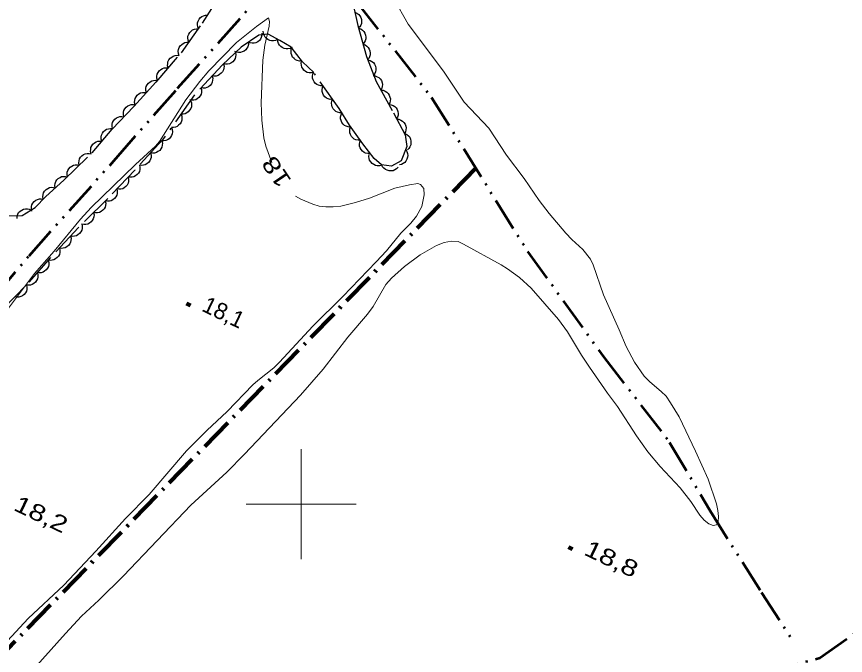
# Model space of a CAD drawing. Extents: x 355726 to 357533, y 5103782 to 5105258.
# Drawn here: x 356374.1 to 356449.5, y 5104986.2 to 5105044.4 of the extents above; entities that cross this region are included whole.
import ezdxf
from ezdxf.enums import TextEntityAlignment as Align

# ---------------------------------------------------------------- set-up
doc = ezdxf.new("R2010")
doc.units = 0
doc.header["$LTSCALE"] = 0.6
for name, pattern in [('DASH_DOUBLE_DOT', [9.2, 5, -1.2, 0.3, -1.2, 0.3, -1.2]), ('DOT_DASHED', [7.7, 5, -1.2, 0.3, -1.2]), ('LONG_DASHED', [7.5, 6, -1.5])]:
    doc.linetypes.add(name, pattern=pattern)
for name, color, linetype, lineweight in [('2', 7, 'LONG_DASHED', 13), ('3', 7, 'Continuous', 140), ('4', 7, 'DASH_DOUBLE_DOT', 53), ('41', 7, 'DOT_DASHED', 90), ('44', 7, 'Continuous', 25), ('61', 7, 'Continuous', 13)]:
    doc.layers.add(name, color=color, linetype=linetype, lineweight=lineweight)

msp = doc.modelspace()

# ---------------------------------------------------------------- linework, layer by layer
at = {"layer": '2', "linetype": 'Continuous'}
for points in [[(356437.94, 5104998.86), (356437.9, 5104999.41), (356437.77, 5105000.04), (356437.01, 5105002.26), (356435.85, 5105004.82), (356434.36, 5105007.93), (356433.6, 5105009.23), (356433.2, 5105009.82), (356432.74, 5105010.26), (356431.7, 5105011.12), (356431.18, 5105011.65), (356430.3, 5105012.92), (356429.56, 5105014.33), (356428.93, 5105015.87), (356427.5, 5105019.05), (356426.55, 5105021.78), (356426.3, 5105022.29), (356425.6, 5105023.16), (356424.6, 5105024.09), (356424.07, 5105024.65), (356422.55, 5105026.46), (356421.65, 5105027.63), (356420.28, 5105029.62), (356418.66, 5105031.76), (356417.05, 5105034.22), (356414.81, 5105036.58), (356412.94, 5105039.41), (356409.72, 5105043.69), (356405.81, 5105050.63)], [(356372.83, 5105017.09), (356375.75, 5105020.98), (356377.54, 5105023.01), (356379.92, 5105025.92), (356380.9, 5105026.98), (356384.92, 5105030.9), (356386.75, 5105032.59), (356387.11, 5105032.99), (356389.51, 5105036.8), (356390.77, 5105038.46), (356391.61, 5105039.43), (356394.12, 5105042), (356395.92, 5105043.46), (356397.03, 5105044.24), (356397.12, 5105043.92), (356397.07, 5105043.51), (356396.7, 5105041.76), (356396.52, 5105040.41), (356396.35, 5105036.51), (356396.41, 5105034.93), (356396.6, 5105033.34), (356396.79, 5105032.59), (356397.34, 5105031.09)], [(356399.48, 5105028.03), (356399.96, 5105027.76), (356401.05, 5105027.29), (356401.62, 5105027.13), (356402.24, 5105027.05), (356402.92, 5105027.04), (356403.59, 5105027.13), (356404.94, 5105027.45), (356406.21, 5105027.84), (356408.52, 5105028.74), (356409.85, 5105029.07), (356410.6, 5105029.17), (356410.86, 5105029.08), (356411.15, 5105028.73), (356411.19, 5105028.16), (356410.96, 5105027.09), (356410.47, 5105026.2), (356409.96, 5105025.58), (356409.07, 5105024.67), (356407.75, 5105023.05), (356406.83, 5105022.05), (356403.79, 5105018.88), (356401.06, 5105016.19), (356398.02, 5105012.92), (356397.5, 5105012.41), (356396.05, 5105011.26), (356395.61, 5105010.86), (356393.25, 5105008.43), (356391.41, 5105006.7), (356389.56, 5105004.84), (356386.18, 5105000.88), (356384.02, 5104998.69), (356381.33, 5104995.71), (356378.42, 5104992.63), (356375.16, 5104989.59), (356369.89, 5104983.93)], [(356375.16, 5104984.42), (356378.55, 5104988.22), (356380.03, 5104989.79), (356381.6, 5104991.26), (356383.84, 5104993.47), (356389.97, 5104999.91), (356393.22, 5105002.9), (356394.84, 5105004.55), (356399.94, 5105009.93), (356402, 5105012.29), (356404.24, 5105015.18), (356406.04, 5105017.3), (356406.53, 5105017.98), (356407.71, 5105019.98), (356408.2, 5105020.55), (356409.4, 5105021.63), (356410.81, 5105022.68), (356412.29, 5105023.54), (356413, 5105023.8), (356413.66, 5105023.94), (356414.27, 5105023.9), (356414.76, 5105023.67), (356418.2, 5105021.78), (356418.77, 5105021.42), (356419.85, 5105020.63), (356420.91, 5105019.65), (356423.39, 5105016.79), (356424.21, 5105015.67), (356425.49, 5105013.55), (356426.21, 5105012.47), (356427.87, 5105010.09), (356428.77, 5105008.88), (356430.5, 5105006.2), (356431.52, 5105004.76), (356432.65, 5105003.42), (356434.48, 5105001.49), (356435.45, 5105000.23), (356436.26, 5104999.01), (356436.65, 5104998.53), (356437.07, 5104998.21), (356437.46, 5104998.05), (356437.78, 5104998.12), (356437.93, 5104998.4), (356437.94, 5104998.86)]]:
    msp.add_lwpolyline(points, dxfattribs=at)
at = {"layer": '3'}
for p, q in [((356389.57, 5105018.25), (356389.93, 5105018.08)), ((356424.32, 5104996.07), (356424.68, 5104995.9))]:
    msp.add_line(p, q, dxfattribs=at)
at = {"layer": '4'}
for points in [[(356339.44, 5104984.41), (356342.57, 5104987.3), (356345.43, 5104989.4), (356348.27, 5104992.55), (356353.06, 5104997.45), (356357.34, 5105001.22), (356361.27, 5105005.44), (356363.86, 5105008.47), (356365.91, 5105011.22), (356369.21, 5105015.05), (356372.09, 5105018.86), (356375.24, 5105022.59), (356382.96, 5105031.25), (356388.75, 5105037.84), (356397.2, 5105047.28), (356402.63, 5105053.37), (356407.19, 5105058.61), (356412.14, 5105064.26), (356419.11, 5105072.16), (356427.79, 5105081.09)], [(356401.2, 5105051.76), (356405.12, 5105045.59), (356411.86, 5105037.01), (356420.59, 5105022.99), (356427.52, 5105013.38), (356433.51, 5105005.62), (356437.18, 5104999.38), (356441.87, 5104991.96), (356444.63, 5104987.67)], [(356336.18, 5104942.45), (356341.96, 5104947.67), (356347.36, 5104952.78), (356353.47, 5104957.09), (356358.77, 5104960.07), (356366.13, 5104963.5), (356374.65, 5104966.38), (356388.16, 5104970.04), (356447.17, 5104986.01), (356457.01, 5104992.96), (356506.13, 5105036.55), (356518.85, 5105048.42), (356518.86, 5105048.43)]]:
    msp.add_lwpolyline(points, dxfattribs=at)
at = {"layer": '41'}
msp.add_line((356415.87, 5105030.57), (356369.66, 5104983.09), dxfattribs=at)
at = {"layer": '44', "linetype": 'DOT_DASHED'}
for points in [[(356372.21, 5105026.22), (356374.61, 5105026.26), (356375.8, 5105026.98), (356376.78, 5105028.01), (356378.4, 5105029.48), (356380.99, 5105031.98), (356382.8, 5105034.13), (356384.76, 5105036.19), (356386.8, 5105038.41), (356389.1, 5105041.08), (356391.01, 5105043.76), (356392.86, 5105046.68)], [(356404.7, 5105045.58), (356405.14, 5105043.55), (356405.93, 5105040.74), (356406.82, 5105038.46), (356408.38, 5105035.6), (356409.44, 5105033.62), (356409.61, 5105032.54), (356409.08, 5105031.25), (356408.21, 5105030.75), (356407.29, 5105030.87), (356406.62, 5105031.44), (356405.61, 5105032.8), (356404.38, 5105034.48), (356403.45, 5105035.99), (356401.14, 5105039.27), (356400.11, 5105040.24), (356399.09, 5105041.6), (356398.04, 5105042.19), (356396.99, 5105042.78), (356396.13, 5105042.67), (356394.53, 5105041.59), (356392.83, 5105039.97), (356390.3, 5105037.24)], [(356390.3, 5105037.24), (356387.39, 5105033.14), (356384.86, 5105030.4), (356382.41, 5105027.82), (356379.73, 5105025.17), (356377.2, 5105022.44), (356374.99, 5105019.92), (356372.13, 5105016.97), (356369.52, 5105014.09), (356366.65, 5105010.76), (356364.1, 5105007.64), (356353.71, 5104995.88), (356350.22, 5104992.5), (356348.03, 5104990.37), (356346, 5104988.54), (356344.73, 5104987.67), (356343.7, 5104987.26), (356342.4, 5104987.4), (356341.65, 5104987.82), (356341.06, 5104988.54), (356341, 5104988.78), (356340.94, 5104990.79)]]:
    msp.add_lwpolyline(points, dxfattribs=at)
at = {"layer": '44'}
for points in [[(356404.88, 5105044.77), (356405.07, 5105044.69), (356405.23, 5105044.56), (356405.34, 5105044.44), (356405.42, 5105044.29), (356405.48, 5105044.11), (356405.49, 5105043.92), (356405.48, 5105043.75), (356405.41, 5105043.59), (356405.32, 5105043.43), (356405.19, 5105043.3)], [(356390.68, 5105043.23), (356390.59, 5105043.43), (356390.57, 5105043.63), (356390.57, 5105043.79), (356390.63, 5105043.96), (356390.71, 5105044.12), (356390.84, 5105044.27), (356390.96, 5105044.38), (356391.12, 5105044.45), (356391.3, 5105044.5), (356391.48, 5105044.5)], [(356389.78, 5105042.03), (356389.71, 5105042.23), (356389.69, 5105042.43), (356389.7, 5105042.6), (356389.77, 5105042.76), (356389.86, 5105042.92), (356390, 5105043.05), (356390.12, 5105043.16), (356390.29, 5105043.22), (356390.47, 5105043.26), (356390.65, 5105043.25)], [(356405.21, 5105043.3), (356405.41, 5105043.24), (356405.57, 5105043.12), (356405.69, 5105043.01), (356405.78, 5105042.86), (356405.85, 5105042.68), (356405.87, 5105042.49), (356405.87, 5105042.33), (356405.82, 5105042.16), (356405.73, 5105042), (356405.62, 5105041.86)], [(356396.43, 5105042.87), (356396.43, 5105042.67), (356396.37, 5105042.47), (356396.3, 5105042.32), (356396.19, 5105042.19), (356396.05, 5105042.07), (356395.87, 5105041.99), (356395.72, 5105041.94), (356395.54, 5105041.94), (356395.36, 5105041.97), (356395.19, 5105042.04)], [(356397.86, 5105042.29), (356397.67, 5105042.2), (356397.47, 5105042.16), (356397.31, 5105042.16), (356397.14, 5105042.2), (356396.97, 5105042.28), (356396.82, 5105042.4), (356396.71, 5105042.51), (356396.62, 5105042.67), (356396.57, 5105042.85), (356396.55, 5105043.03)], [(356388.91, 5105040.81), (356388.83, 5105041.01), (356388.82, 5105041.21), (356388.83, 5105041.37), (356388.9, 5105041.54), (356388.99, 5105041.7), (356389.13, 5105041.83), (356389.25, 5105041.93), (356389.42, 5105042), (356389.6, 5105042.04), (356389.78, 5105042.03)], [(356395.19, 5105042.04), (356395.19, 5105041.83), (356395.13, 5105041.63), (356395.06, 5105041.48), (356394.95, 5105041.35), (356394.8, 5105041.23), (356394.63, 5105041.15), (356394.47, 5105041.1), (356394.3, 5105041.1), (356394.11, 5105041.13), (356393.95, 5105041.2)], [(356399.17, 5105041.56), (356398.98, 5105041.46), (356398.78, 5105041.43), (356398.62, 5105041.42), (356398.45, 5105041.47), (356398.28, 5105041.54), (356398.13, 5105041.66), (356398.01, 5105041.78), (356397.93, 5105041.93), (356397.88, 5105042.11), (356397.86, 5105042.29)], [(356405.62, 5105041.86), (356405.81, 5105041.79), (356405.98, 5105041.68), (356406.1, 5105041.56), (356406.19, 5105041.41), (356406.25, 5105041.24), (356406.28, 5105041.05), (356406.28, 5105040.89), (356406.22, 5105040.72), (356406.14, 5105040.55), (356406.02, 5105040.42)], [(356387.9, 5105039.69), (356387.85, 5105039.89), (356387.86, 5105040.1), (356387.88, 5105040.26), (356387.96, 5105040.42), (356388.07, 5105040.57), (356388.22, 5105040.69), (356388.35, 5105040.78), (356388.52, 5105040.83), (356388.71, 5105040.85), (356388.88, 5105040.83)], [(356394.02, 5105041.1), (356394.06, 5105040.9), (356394.03, 5105040.7), (356393.99, 5105040.54), (356393.89, 5105040.39), (356393.77, 5105040.25), (356393.61, 5105040.14), (356393.47, 5105040.07), (356393.3, 5105040.03), (356393.11, 5105040.03), (356392.93, 5105040.07)], [(356400.04, 5105040.33), (356399.84, 5105040.32), (356399.64, 5105040.37), (356399.48, 5105040.43), (356399.35, 5105040.54), (356399.22, 5105040.68), (356399.14, 5105040.85), (356399.08, 5105041), (356399.07, 5105041.17), (356399.09, 5105041.36), (356399.14, 5105041.53)], [(356401.12, 5105039.29), (356400.92, 5105039.24), (356400.72, 5105039.26), (356400.55, 5105039.29), (356400.4, 5105039.37), (356400.25, 5105039.49), (356400.14, 5105039.64), (356400.05, 5105039.78), (356400.01, 5105039.95), (356400, 5105040.14), (356400.03, 5105040.32)], [(356406.05, 5105040.43), (356406.26, 5105040.38), (356406.43, 5105040.28), (356406.56, 5105040.18), (356406.67, 5105040.04), (356406.75, 5105039.87), (356406.79, 5105039.68), (356406.8, 5105039.52), (356406.77, 5105039.35), (356406.7, 5105039.18), (356406.6, 5105039.03)], [(356386.93, 5105038.56), (356386.87, 5105038.76), (356386.88, 5105038.96), (356386.9, 5105039.12), (356386.98, 5105039.28), (356387.09, 5105039.43), (356387.24, 5105039.55), (356387.37, 5105039.64), (356387.54, 5105039.69), (356387.73, 5105039.71), (356387.9, 5105039.69)], [(356392.93, 5105040.08), (356392.98, 5105039.87), (356392.96, 5105039.67), (356392.93, 5105039.51), (356392.85, 5105039.35), (356392.73, 5105039.21), (356392.58, 5105039.09), (356392.44, 5105039), (356392.27, 5105038.96), (356392.09, 5105038.95), (356391.91, 5105038.98)], [(356385.92, 5105037.45), (356385.87, 5105037.65), (356385.88, 5105037.85), (356385.91, 5105038.02), (356385.99, 5105038.17), (356386.11, 5105038.32), (356386.26, 5105038.44), (356386.4, 5105038.52), (356386.57, 5105038.56), (356386.75, 5105038.58), (356386.93, 5105038.55)], [(356391.91, 5105038.98), (356391.96, 5105038.77), (356391.94, 5105038.57), (356391.91, 5105038.41), (356391.83, 5105038.25), (356391.71, 5105038.11), (356391.56, 5105037.99), (356391.42, 5105037.9), (356391.25, 5105037.86), (356391.07, 5105037.85), (356390.89, 5105037.88)], [(356401.99, 5105038.06), (356401.78, 5105038.06), (356401.58, 5105038.12), (356401.43, 5105038.18), (356401.3, 5105038.29), (356401.18, 5105038.44), (356401.1, 5105038.61), (356401.04, 5105038.76), (356401.04, 5105038.94), (356401.06, 5105039.12), (356401.13, 5105039.29)], [(356406.53, 5105039), (356406.74, 5105038.98), (356406.92, 5105038.9), (356407.07, 5105038.82), (356407.19, 5105038.69), (356407.29, 5105038.54), (356407.35, 5105038.35), (356407.39, 5105038.19), (356407.37, 5105038.02), (356407.33, 5105037.84), (356407.25, 5105037.68)], [(356390.89, 5105037.88), (356390.94, 5105037.67), (356390.92, 5105037.47), (356390.89, 5105037.31), (356390.81, 5105037.15), (356390.69, 5105037.01), (356390.54, 5105036.89), (356390.4, 5105036.8), (356390.23, 5105036.76), (356390.05, 5105036.75), (356389.87, 5105036.78)], [(356402.85, 5105036.84), (356402.64, 5105036.83), (356402.45, 5105036.89), (356402.3, 5105036.95), (356402.16, 5105037.07), (356402.04, 5105037.21), (356401.96, 5105037.38), (356401.91, 5105037.54), (356401.9, 5105037.71), (356401.93, 5105037.9), (356401.99, 5105038.06)], [(356384.9, 5105036.34), (356384.85, 5105036.55), (356384.87, 5105036.75), (356384.9, 5105036.91), (356384.98, 5105037.07), (356385.09, 5105037.21), (356385.24, 5105037.33), (356385.38, 5105037.42), (356385.55, 5105037.46), (356385.74, 5105037.47), (356385.92, 5105037.45)], [(356407.25, 5105037.68), (356407.45, 5105037.66), (356407.64, 5105037.58), (356407.78, 5105037.5), (356407.91, 5105037.37), (356408.01, 5105037.22), (356408.07, 5105037.04), (356408.11, 5105036.88), (356408.09, 5105036.7), (356408.05, 5105036.52), (356407.96, 5105036.36)], [(356383.87, 5105035.25), (356383.82, 5105035.46), (356383.84, 5105035.66), (356383.88, 5105035.82), (356383.96, 5105035.98), (356384.08, 5105036.12), (356384.23, 5105036.24), (356384.37, 5105036.32), (356384.54, 5105036.36), (356384.73, 5105036.37), (356384.9, 5105036.34)], [(356389.93, 5105036.72), (356390.01, 5105036.53), (356390.02, 5105036.32), (356390.01, 5105036.16), (356389.95, 5105036), (356389.85, 5105035.84), (356389.72, 5105035.7), (356389.59, 5105035.6), (356389.43, 5105035.53), (356389.25, 5105035.5), (356389.07, 5105035.5)], [(356403.72, 5105035.61), (356403.51, 5105035.61), (356403.31, 5105035.66), (356403.16, 5105035.73), (356403.03, 5105035.84), (356402.91, 5105035.98), (356402.82, 5105036.16), (356402.77, 5105036.31), (356402.76, 5105036.49), (356402.79, 5105036.67), (356402.85, 5105036.84)], [(356407.96, 5105036.36), (356408.17, 5105036.34), (356408.36, 5105036.27), (356408.5, 5105036.18), (356408.62, 5105036.06), (356408.73, 5105035.9), (356408.79, 5105035.72), (356408.82, 5105035.56), (356408.81, 5105035.39), (356408.76, 5105035.21), (356408.68, 5105035.05)], [(356404.48, 5105034.32), (356404.27, 5105034.33), (356404.08, 5105034.39), (356403.93, 5105034.47), (356403.8, 5105034.59), (356403.69, 5105034.74), (356403.62, 5105034.92), (356403.58, 5105035.07), (356403.58, 5105035.25), (356403.62, 5105035.43), (356403.69, 5105035.6)], [(356382.84, 5105034.17), (356382.79, 5105034.37), (356382.81, 5105034.57), (356382.84, 5105034.74), (356382.93, 5105034.89), (356383.04, 5105035.03), (356383.19, 5105035.15), (356383.34, 5105035.23), (356383.51, 5105035.27), (356383.69, 5105035.28), (356383.87, 5105035.25)], [(356389.07, 5105035.5), (356389.14, 5105035.3), (356389.15, 5105035.1), (356389.14, 5105034.94), (356389.08, 5105034.77), (356388.98, 5105034.61), (356388.85, 5105034.48), (356388.72, 5105034.37), (356388.56, 5105034.31), (356388.38, 5105034.27), (356388.2, 5105034.28)], [(356408.68, 5105035.04), (356408.89, 5105035.02), (356409.07, 5105034.94), (356409.22, 5105034.86), (356409.34, 5105034.73), (356409.44, 5105034.58), (356409.5, 5105034.39), (356409.53, 5105034.24), (356409.52, 5105034.06), (356409.47, 5105033.88), (356409.39, 5105033.72)], [(356381.87, 5105033.02), (356381.81, 5105033.22), (356381.81, 5105033.43), (356381.84, 5105033.59), (356381.91, 5105033.75), (356382.02, 5105033.9), (356382.17, 5105034.02), (356382.3, 5105034.12), (356382.47, 5105034.16), (356382.65, 5105034.19), (356382.83, 5105034.17)], [(356388.2, 5105034.28), (356388.27, 5105034.08), (356388.28, 5105033.88), (356388.27, 5105033.71), (356388.21, 5105033.55), (356388.12, 5105033.39), (356387.98, 5105033.25), (356387.85, 5105033.15), (356387.69, 5105033.09), (356387.51, 5105033.05), (356387.33, 5105033.05)], [(356405.38, 5105033.12), (356405.17, 5105033.11), (356404.97, 5105033.16), (356404.82, 5105033.22), (356404.68, 5105033.33), (356404.56, 5105033.47), (356404.48, 5105033.64), (356404.42, 5105033.8), (356404.41, 5105033.97), (356404.43, 5105034.16), (356404.49, 5105034.33)], [(356409.42, 5105033.73), (356409.61, 5105033.64), (356409.76, 5105033.51), (356409.87, 5105033.38), (356409.94, 5105033.22), (356409.98, 5105033.04), (356409.98, 5105032.85), (356409.96, 5105032.69), (356409.89, 5105032.53), (356409.79, 5105032.37), (356409.66, 5105032.25)], [(356380.9, 5105031.87), (356380.84, 5105032.08), (356380.85, 5105032.28), (356380.87, 5105032.44), (356380.95, 5105032.6), (356381.05, 5105032.75), (356381.2, 5105032.88), (356381.34, 5105032.97), (356381.5, 5105033.02), (356381.69, 5105033.04), (356381.87, 5105033.02)], [(356387.32, 5105033.06), (356387.37, 5105032.86), (356387.35, 5105032.66), (356387.32, 5105032.49), (356387.24, 5105032.34), (356387.13, 5105032.19), (356386.97, 5105032.08), (356386.83, 5105031.99), (356386.66, 5105031.95), (356386.48, 5105031.93), (356386.3, 5105031.96)], [(356406.27, 5105031.91), (356406.06, 5105031.9), (356405.86, 5105031.95), (356405.71, 5105032.01), (356405.57, 5105032.12), (356405.45, 5105032.26), (356405.36, 5105032.43), (356405.31, 5105032.58), (356405.3, 5105032.76), (356405.32, 5105032.95), (356405.38, 5105033.11)], [(356379.81, 5105030.84), (356379.78, 5105031.05), (356379.8, 5105031.25), (356379.84, 5105031.41), (356379.93, 5105031.56), (356380.05, 5105031.7), (356380.21, 5105031.81), (356380.36, 5105031.88), (356380.53, 5105031.92), (356380.71, 5105031.92), (356380.89, 5105031.88)], [(356386.3, 5105031.96), (356386.35, 5105031.76), (356386.34, 5105031.55), (356386.3, 5105031.39), (356386.22, 5105031.24), (356386.11, 5105031.09), (356385.96, 5105030.97), (356385.82, 5105030.89), (356385.65, 5105030.85), (356385.46, 5105030.83), (356385.28, 5105030.86)], [(356407.32, 5105030.85), (356407.11, 5105030.79), (356406.91, 5105030.8), (356406.75, 5105030.82), (356406.59, 5105030.9), (356406.44, 5105031.01), (356406.32, 5105031.15), (356406.22, 5105031.29), (356406.18, 5105031.46), (356406.15, 5105031.64), (356406.17, 5105031.82)], [(356409.5, 5105032.27), (356409.61, 5105032.1), (356409.67, 5105031.9), (356409.7, 5105031.74), (356409.68, 5105031.56), (356409.62, 5105031.39), (356409.52, 5105031.22), (356409.42, 5105031.1), (356409.27, 5105031), (356409.11, 5105030.92), (356408.93, 5105030.88)], [(356378.73, 5105029.8), (356378.7, 5105030.01), (356378.72, 5105030.21), (356378.76, 5105030.37), (356378.85, 5105030.52), (356378.97, 5105030.66), (356379.13, 5105030.77), (356379.28, 5105030.84), (356379.45, 5105030.88), (356379.64, 5105030.88), (356379.81, 5105030.84)], [(356385.29, 5105030.85), (356385.33, 5105030.65), (356385.32, 5105030.45), (356385.28, 5105030.28), (356385.2, 5105030.13), (356385.08, 5105029.99), (356384.93, 5105029.87), (356384.79, 5105029.79), (356384.62, 5105029.75), (356384.43, 5105029.74), (356384.26, 5105029.76)], [(356408.81, 5105030.67), (356408.67, 5105030.52), (356408.5, 5105030.41), (356408.35, 5105030.34), (356408.17, 5105030.32), (356407.99, 5105030.33), (356407.81, 5105030.38), (356407.66, 5105030.45), (356407.52, 5105030.56), (356407.4, 5105030.7), (356407.32, 5105030.87)], [(356377.63, 5105028.78), (356377.6, 5105028.99), (356377.63, 5105029.19), (356377.68, 5105029.35), (356377.77, 5105029.5), (356377.9, 5105029.63), (356378.06, 5105029.73), (356378.21, 5105029.81), (356378.38, 5105029.83), (356378.57, 5105029.83), (356378.74, 5105029.79)], [(356384.26, 5105029.76), (356384.3, 5105029.56), (356384.29, 5105029.36), (356384.25, 5105029.2), (356384.17, 5105029.04), (356384.05, 5105028.9), (356383.9, 5105028.78), (356383.76, 5105028.7), (356383.59, 5105028.66), (356383.4, 5105028.65), (356383.22, 5105028.68)], [(356376.52, 5105027.77), (356376.49, 5105027.98), (356376.52, 5105028.18), (356376.57, 5105028.34), (356376.66, 5105028.49), (356376.79, 5105028.62), (356376.95, 5105028.73), (356377.1, 5105028.8), (356377.27, 5105028.83), (356377.46, 5105028.82), (356377.63, 5105028.78)], [(356383.22, 5105028.68), (356383.27, 5105028.47), (356383.25, 5105028.27), (356383.22, 5105028.11), (356383.13, 5105027.95), (356383.02, 5105027.81), (356382.86, 5105027.69), (356382.72, 5105027.61), (356382.55, 5105027.57), (356382.37, 5105027.56), (356382.19, 5105027.59)], [(356375.5, 5105026.67), (356375.46, 5105026.87), (356375.48, 5105027.08), (356375.51, 5105027.24), (356375.6, 5105027.39), (356375.71, 5105027.54), (356375.86, 5105027.65), (356376, 5105027.73), (356376.18, 5105027.77), (356376.36, 5105027.79), (356376.54, 5105027.76)], [(356382.18, 5105027.6), (356382.22, 5105027.39), (356382.2, 5105027.19), (356382.16, 5105027.03), (356382.07, 5105026.88), (356381.95, 5105026.74), (356381.79, 5105026.63), (356381.65, 5105026.55), (356381.48, 5105026.51), (356381.29, 5105026.51), (356381.12, 5105026.54)], [(356374.15, 5105025.98), (356374.16, 5105026.19), (356374.23, 5105026.38), (356374.3, 5105026.53), (356374.43, 5105026.65), (356374.58, 5105026.76), (356374.75, 5105026.83), (356374.91, 5105026.88), (356375.09, 5105026.87), (356375.27, 5105026.83), (356375.43, 5105026.76)], [(356381.12, 5105026.54), (356381.16, 5105026.34), (356381.13, 5105026.13), (356381.09, 5105025.97), (356381, 5105025.82), (356380.88, 5105025.68), (356380.73, 5105025.57), (356380.58, 5105025.49), (356380.41, 5105025.46), (356380.23, 5105025.45), (356380.05, 5105025.49)], [(356380.04, 5105025.5), (356380.08, 5105025.3), (356380.07, 5105025.09), (356380.04, 5105024.93), (356379.95, 5105024.78), (356379.84, 5105024.63), (356379.69, 5105024.51), (356379.55, 5105024.43), (356379.38, 5105024.39), (356379.19, 5105024.37), (356379.02, 5105024.4)], [(356379.02, 5105024.4), (356379.06, 5105024.2), (356379.05, 5105023.99), (356379.02, 5105023.83), (356378.94, 5105023.68), (356378.82, 5105023.53), (356378.67, 5105023.41), (356378.53, 5105023.33), (356378.36, 5105023.29), (356378.17, 5105023.27), (356378, 5105023.3)], [(356378, 5105023.3), (356378.04, 5105023.1), (356378.03, 5105022.89), (356378, 5105022.73), (356377.92, 5105022.58), (356377.8, 5105022.43), (356377.65, 5105022.31), (356377.51, 5105022.23), (356377.34, 5105022.19), (356377.16, 5105022.17), (356376.98, 5105022.2)], [(356376.98, 5105022.19), (356377.04, 5105021.99), (356377.03, 5105021.79), (356377, 5105021.63), (356376.92, 5105021.47), (356376.81, 5105021.32), (356376.66, 5105021.2), (356376.53, 5105021.11), (356376.36, 5105021.06), (356376.17, 5105021.04), (356376, 5105021.07)], [(356376, 5105021.07), (356376.05, 5105020.86), (356376.04, 5105020.66), (356376.01, 5105020.5), (356375.93, 5105020.34), (356375.82, 5105020.19), (356375.68, 5105020.07), (356375.54, 5105019.98), (356375.37, 5105019.94), (356375.18, 5105019.92), (356375.01, 5105019.94)], [(356375.01, 5105019.94), (356375.05, 5105019.73), (356375.03, 5105019.53), (356375, 5105019.37), (356374.91, 5105019.22), (356374.79, 5105019.07), (356374.64, 5105018.96), (356374.5, 5105018.88), (356374.33, 5105018.84), (356374.14, 5105018.83), (356373.96, 5105018.86)]]:
    msp.add_lwpolyline(points, dxfattribs=at)
at = {"layer": '61'}
for p, q in [((356400, 5104995), (356400, 5105005)), ((356395, 5105000), (356405, 5105000))]:
    msp.add_line(p, q, dxfattribs=at)

# ---------------------------------------------------------------- texts
at = {"layer": '2', "width": 1.3}
msp.add_text('18', height=1.5, rotation=124.196, dxfattribs=at).set_placement((356398.359, 5105030.644), align=Align.CENTER)
at = {"layer": '3'}
msp.add_text('18,1   ', height=1.5, rotation=334.423, dxfattribs=at).set_placement((356390.86, 5105017.62))
at = {"layer": '3', "width": 1.3}
for s, p in [('18,2   ', (356373.73, 5104999.5)), ('18,8   ', (356425.61, 5104995.44))]:
    msp.add_text(s, height=1.5, rotation=334.423, dxfattribs=at).set_placement(p)

doc.saveas('drawing.dxf')
